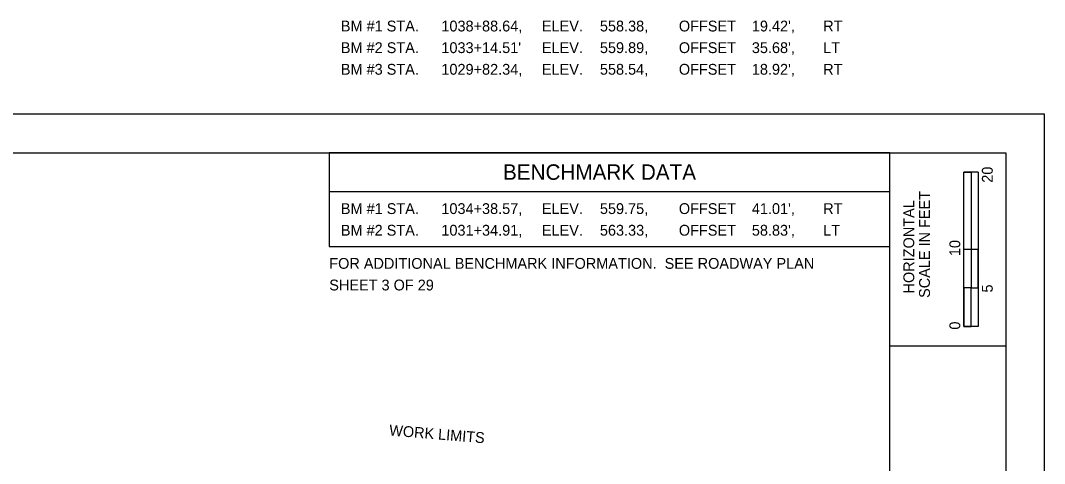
# Model space of a CAD drawing. Extents: x 0 to 2360, y -10 to 232.
# Drawn here: x 207.6 to 340, y 174.8 to 232.1 of the extents above; entities that cross this region are included whole.
import ezdxf

# ---------------------------------------------------------------- set-up
doc = ezdxf.new("R2010")
doc.units = 0
for name, color, linetype in [('BR_P_Brg_Centerline', 7, 'Continuous'), ('BR_P_Sub_Backwall', 7, 'Continuous'), ('MT_P_PCB', 7, 'Continuous'), ('TX_P_1', 7, 'Continuous')]:
    doc.layers.add(name, color=color, linetype=linetype)

msp = doc.modelspace()

# ---------------------------------------------------------------- linework, layer by layer
at = {"layer": 'BR_P_Brg_Centerline'}
msp.add_lwpolyline([(0, 0), (340, 0), (340, 220), (0, 220)], close=True, dxfattribs=at)
at = {"layer": 'BR_P_Sub_Backwall'}
for p, q in [((320, 215), (247.5, 215)), ((247.5, 215), (247.5, 202.87)), ((320, 197.27), (320, 215)), ((329.57, 202.5), (329.57, 212.5)), ((329.57, 212.5), (330.5, 212.5)), ((329.57, 192.5), (329.57, 212.5)), ((331.44, 212.5), (329.57, 212.5)), ((330.5, 212.5), (330.51, 212.5)), ((330.51, 212.5), (330.51, 202.5)), ((331.44, 212.5), (331.44, 192.5)), ((247.5, 210), (320, 210)), ((247.5, 202.87), (320, 202.87)), ((330.51, 202.5), (329.57, 202.5)), ((331.43, 202.5), (330.5, 202.5)), ((330.5, 202.5), (330.5, 197.5)), ((331.43, 197.5), (331.43, 202.5)), ((330.5, 197.5), (329.57, 197.5)), ((329.57, 197.5), (329.57, 192.5)), ((330.5, 197.5), (331.43, 197.5)), ((330.5, 192.5), (330.5, 197.5)), ((331.44, 192.5), (329.57, 192.5)), ((329.57, 192.5), (330.5, 192.5))]:
    msp.add_line(p, q, dxfattribs=at)
at = {"layer": 'TX_P_1'}
for p, q in [((320, 5), (320, 215)), ((320, 190), (335, 190))]:
    msp.add_line(p, q, dxfattribs=at)
msp.add_lwpolyline([(15, 215), (335, 215), (335, 5), (15, 5)], close=True, dxfattribs=at)

# ---------------------------------------------------------------- texts
at = {"layer": 'BR_P_Sub_Backwall'}
for s, height, p in [('BM #1 STA.', 1.4, (249, 230.7)), ('1038+88.64,', 1.4, (262, 230.7)), ('ELEV.', 1.4, (275, 230.7)), ('558.38,', 1.4, (282.5, 230.7)), ('OFFSET', 1.4, (292.71, 230.7)), ("19.42',", 1.4, (302.15, 230.7)), ('RT', 1.4, (311.38, 230.7)), ('BM #2 STA.', 1.4, (249, 227.9)), ("1033+14.51'", 1.4, (262, 227.9)), ('ELEV.', 1.4, (275, 227.9)), ('559.89,', 1.4, (282.5, 227.9)), ('OFFSET', 1.4, (292.71, 227.9)), ("35.68',", 1.4, (302.15, 227.9)), ('LT', 1.4, (311.38, 227.9)), ('BM #3 STA.', 1.4, (249, 225.1)), ('1029+82.34,', 1.4, (262, 225.1)), ('ELEV.', 1.4, (275, 225.1)), ('558.54,', 1.4, (282.5, 225.1)), ('OFFSET', 1.4, (292.71, 225.1)), ("18.92',", 1.4, (302.15, 225.1)), ('RT', 1.4, (311.38, 225.1)), ('BENCHMARK DATA', 2, (269.97, 211.5)), ('BM #1 STA.', 1.4, (249, 207.07)), ('1034+38.57,', 1.4, (262, 207.07)), ('ELEV.', 1.4, (275, 207.07)), ('559.75,', 1.4, (282.5, 207.07)), ('OFFSET', 1.4, (292.71, 207.07)), ("41.01',", 1.4, (302.15, 207.07)), ('RT', 1.4, (311.38, 207.07)), ('BM #2 STA.', 1.4, (249, 204.27)), ('1031+34.91,', 1.4, (262, 204.27)), ('ELEV.', 1.4, (275, 204.27)), ('563.33,', 1.4, (282.5, 204.27)), ('OFFSET', 1.4, (292.71, 204.27)), ("58.83',", 1.4, (302.15, 204.27)), ('LT', 1.4, (311.38, 204.27)), ('FOR ADDITIONAL BENCHMARK INFORMATION.  SEE ROADWAY PLAN', 1.4, (247.5, 199.98)), ('SHEET 3 OF 29', 1.4, (247.5, 197.18))]:
    msp.add_text(s, height=height, dxfattribs=at).set_placement(p)
for s, p in [('20', (333.3, 211.12)), ('SCALE IN FEET', (325.18, 196.21)), ('HORIZONTAL', (323.15, 196.79)), ('10', (329.1, 201.62)), ('5', (333.3, 196.91)), ('0', (329.1, 192.11))]:
    msp.add_text(s, height=1.4, rotation=90, dxfattribs=at).set_placement(p)
at = {"layer": 'MT_P_PCB'}
msp.add_text('WORK LIMITS', height=1.4, rotation=355.3227, dxfattribs=at).set_placement((255.21, 178.41))

doc.saveas('drawing.dxf')
